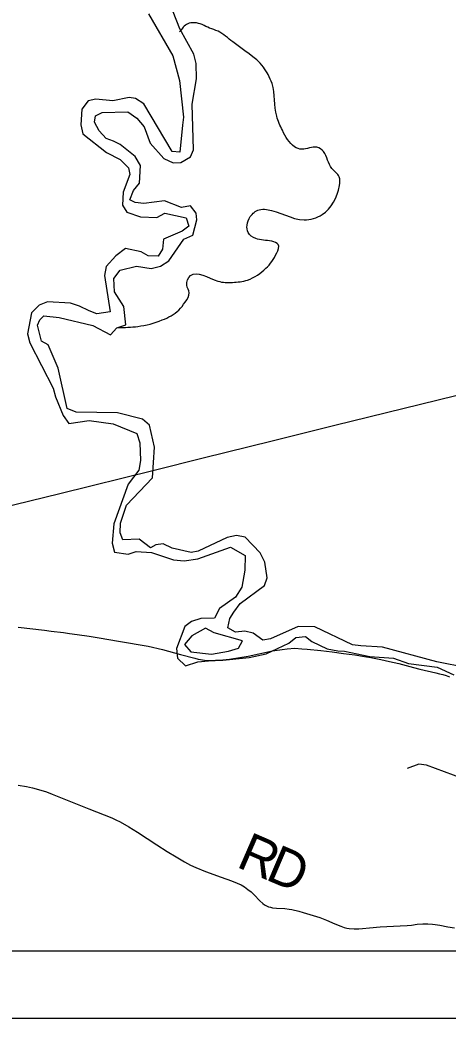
# Model space of a CAD drawing. Extents: x 0 to 34, y 0 to 22.
# Drawn here: x 4.8 to 5.439, y 14 to 15.488 of the extents above; entities that cross this region are included whole.
import ezdxf

# ---------------------------------------------------------------- set-up
doc = ezdxf.new("R2010")
doc.units = 0
for name, color, linetype in [('GM_X_Corporation', 7, 'Continuous'), ('GM_X_County_Road', 7, 'Continuous'), ('GM_X_Minor_River', 7, 'Continuous'), ('GM_X_Rail_Line', 7, 'Continuous'), ('GM_X_Township_Road', 7, 'Continuous'), ('GM_X_Township_Road_Text', 7, 'Continuous'), ('SH_Data', 7, 'Continuous')]:
    doc.layers.add(name, color=color, linetype=linetype)

msp = doc.modelspace()

# ---------------------------------------------------------------- linework, layer by layer
at = {"layer": 'GM_X_Corporation'}
for points in [[(2.1, 16.4477), (2.1, 14.1), (8.9, 14.1), (8.9, 16.2485)], [(2.1, 14.1), (5.9669, 14.1), (5.9718, 14.2339), (5.9719, 14.2518), (5.9912, 14.2433), (6.0106, 14.2347), (6.0457, 14.2204), (6.0638, 14.2101), (6.0897, 14.1893), (6.1001, 14.176), (6.1365, 14.1664), (6.1722, 14.163), (6.1971, 14.165), (6.2589, 14.1491), (6.3803, 14.132), (6.4075, 14.1583), (6.4485, 14.2016), (6.4833, 14.2331), (6.5212, 14.2247), (6.5417, 14.1767), (6.5313, 14.1149), (6.5592, 14.1021), (6.5997, 14.1245)]]:
    msp.add_lwpolyline(points, dxfattribs=at)
at = {"layer": 'GM_X_County_Road'}
msp.add_lwpolyline([(4.7978, 14.583), (4.8371, 14.5782), (4.847, 14.5769), (4.8651, 14.5746), (4.8743, 14.5735), (4.8855, 14.5719), (4.9034, 14.5694), (4.9185, 14.5667), (4.9472, 14.5621), (4.9917, 14.5544), (5.0129, 14.5496), (5.0399, 14.5422), (5.0608, 14.5364), (5.0662, 14.5351), (5.0694, 14.5344), (5.0756, 14.5337), (5.0852, 14.5332), (5.0913, 14.5332), (5.0976, 14.5334), (5.1129, 14.5351), (5.1404, 14.5397), (5.1769, 14.5473), (5.1913, 14.5494), (5.1989, 14.5504), (5.2103, 14.5513), (5.2206, 14.5507), (5.2286, 14.55), (5.249, 14.548), (5.266, 14.5459), (5.2827, 14.5437), (5.2994, 14.5413), (5.3141, 14.5389), (5.3236, 14.5374), (5.3386, 14.5347), (5.3513, 14.5318), (5.3651, 14.5285), (5.3873, 14.5226), (5.3964, 14.5201), (5.4206, 14.5148), (5.4259, 14.5134), (5.431, 14.512), (5.4356, 14.5106), (5.4406, 14.5089)], dxfattribs=at)
at = {"layer": 'GM_X_Minor_River'}
for points in [[(4.9921, 15.4975), (5.028, 15.4346), (5.0384, 15.3978), (5.0439, 15.3432), (5.0428, 15.3315), (5.0388, 15.2912), (5.0271, 15.292), (4.9848, 15.3631), (4.9726, 15.3711), (4.9631, 15.3725), (4.9389, 15.3675), (4.9132, 15.3701), (4.9022, 15.3678), (4.8924, 15.3552), (4.891, 15.3317), (4.8941, 15.3184), (4.9294, 15.2905), (4.9495, 15.2803), (4.9621, 15.2675), (4.964, 15.2576), (4.9543, 15.2314), (4.9532, 15.212), (4.9597, 15.2014), (4.9798, 15.1947), (5.0044, 15.1936), (5.0161, 15.2001), (5.048, 15.193), (5.0522, 15.1809), (5.042, 15.1733), (5.0144, 15.1614), (5.0126, 15.1462), (5.0066, 15.136), (4.9914, 15.1367), (4.9808, 15.1423), (4.9577, 15.1476), (4.943, 15.1365), (4.929, 15.1205), (4.9261, 15.1072)], [(4.9449, 15.0292), (4.9582, 15.0337), (4.9554, 15.0607), (4.9413, 15.083), (4.9401, 15.1027), (4.9499, 15.1153), (4.9741, 15.1211), (4.9957, 15.1177), (5.0097, 15.1212), (5.0225, 15.1292), (5.0447, 15.1615), (5.0579, 15.1673), (5.0642, 15.19), (5.0631, 15.1999), (5.0547, 15.2109), (5.0411, 15.2085), (5.0159, 15.2186), (4.9849, 15.2144), (4.9722, 15.2158), (4.9642, 15.22), (4.9698, 15.2341), (4.9785, 15.2448), (4.9799, 15.2713), (4.9722, 15.2846), (4.9498, 15.3023), (4.94, 15.3072), (4.929, 15.3113), (4.9183, 15.3227), (4.9114, 15.3356), (4.9129, 15.3451), (4.9231, 15.35), (4.961, 15.3513), (4.9746, 15.3419), (4.9857, 15.329), (4.9945, 15.3047), (5.015, 15.2817), (5.0287, 15.2753), (5.04, 15.2757), (5.0548, 15.2841), (5.0593, 15.2947), (5.0571, 15.3626), (5.0637, 15.4006), (5.0632, 15.423), (5.0598, 15.437), (5.0388, 15.4749), (5.0288, 15.5002)], [(4.9261, 15.1072), (4.9346, 15.053), (4.9149, 15.0499), (4.9036, 15.0544), (4.8892, 15.0612), (4.8755, 15.0657), (4.8414, 15.0679), (4.829, 15.0629), (4.8177, 15.0515), (4.8113, 15.0203), (4.8148, 15.0067), (4.8496, 14.9393), (4.8534, 14.926), (4.8645, 14.8984), (4.8733, 14.8863), (4.9035, 14.8909), (4.9391, 14.8861), (4.9744, 14.8714), (4.979, 14.8574), (4.9802, 14.8312), (4.9773, 14.8168), (4.9618, 14.7959), (4.9405, 14.737), (4.9376, 14.7082), (4.9411, 14.6945), (4.9615, 14.6916), (4.9736, 14.6958), (4.9963, 14.6943), (5.0096, 14.6895), (5.0293, 14.6831), (5.0449, 14.6816), (5.0657, 14.6847), (5.1144, 14.702), (5.1361, 14.6895), (5.1358, 14.6679), (5.131, 14.6424), (5.1216, 14.6276), (5.0978, 14.6108), (5.0906, 14.5964), (5.0698, 14.5956), (5.0562, 14.5913), (5.046, 14.5837), (5.0337, 14.5511), (5.0353, 14.5366), (5.047, 14.5249), (5.0656, 14.5311), (5.0921, 14.5334), (5.1027, 14.5335), (5.142, 14.5374), (5.1673, 14.5432), (5.201, 14.5588), (5.2115, 14.5676), (5.2259, 14.5688), (5.2354, 14.5612), (5.2582, 14.5507), (5.2741, 14.5477), (5.2843, 14.547), (5.3218, 14.5391), (5.3574, 14.5366), (5.3798, 14.5287), (5.4226, 14.5232), (5.4472, 14.5119)], [(5.4673, 14.5222), (5.4218, 14.5311), (5.3407, 14.5529), (5.3085, 14.555), (5.296, 14.5565), (5.2402, 14.5833), (5.2152, 14.5839), (5.1737, 14.5652), (5.1623, 14.5633), (5.1479, 14.5738), (5.1354, 14.5768), (5.1218, 14.5753), (5.1104, 14.5817), (5.113, 14.5957), (5.1194, 14.6052), (5.1288, 14.6182), (5.165, 14.6448), (5.1688, 14.6562), (5.1652, 14.6797), (5.1584, 14.6934), (5.1363, 14.7172), (5.1234, 14.7194), (5.1094, 14.7167), (5.066, 14.6961), (5.0558, 14.6942), (5.0274, 14.7005), (5.0137, 14.7069), (5.0027, 14.7057), (4.9947, 14.7011), (4.9778, 14.7138), (4.9539, 14.7132), (4.9497, 14.7234), (4.95, 14.7378), (4.9593, 14.7648), (4.9981, 14.8055), (5.001, 14.851), (4.9933, 14.884), (4.983, 14.8931), (4.9455, 14.9024), (4.8842, 14.9034), (4.8705, 14.909), (4.8574, 14.9689), (4.8421, 15.0038), (4.8326, 15.0094), (4.8263, 15.0333), (4.83, 15.0408), (4.8358, 15.047), (4.8589, 15.0444), (4.909, 15.0328), (4.9351, 15.0189), (4.9449, 15.0292)], [(5.09, 14.5744), (5.0767, 14.5812), (5.0567, 14.5701), (5.0454, 14.5568), (5.0553, 14.5462), (5.086, 14.5425), (5.1113, 14.5468)], [(5.1113, 14.5468), (5.126, 14.5514), (5.1321, 14.5624), (5.09, 14.5744)], [(5.8685, 14.2527), (5.868, 14.2236), (5.829, 14.2071), (5.7855, 14.177), (5.7727, 14.172), (5.7225, 14.1957), (5.71, 14.2039), (5.697, 14.2198), (5.6723, 14.2451), (5.6575, 14.253), (5.6445, 14.2655), (5.6229, 14.2726), (5.5986, 14.2759), (5.5621, 14.2909), (5.4948, 14.3381), (5.4849, 14.3445), (5.4735, 14.3524), (5.4063, 14.3771), (5.3953, 14.3786), (5.3779, 14.3721)]]:
    msp.add_lwpolyline(points, dxfattribs=at)
for points in [[(5.0831, 15.4758), (5.0603, 15.484), (5.0505, 15.4825), (5.0384, 15.4703)], [(4.9463, 15.0296), (4.976, 15.0312), (5.0123, 15.0408), (5.0372, 15.0556), (5.0466, 15.0674), (5.0526, 15.0815), (5.0491, 15.0925), (5.0544, 15.1069), (5.0953, 15.0987), (5.1173, 15.0969), (5.1396, 15.1004), (5.1671, 15.1179), (5.1833, 15.1408), (5.1855, 15.1533), (5.1757, 15.1582), (5.1518, 15.1623), (5.1404, 15.1713), (5.1389, 15.1823), (5.1437, 15.1949), (5.1569, 15.2052), (5.1679, 15.2056), (5.224, 15.1902), (5.2508, 15.1979), (5.2768, 15.2412), (5.2763, 15.2545), (5.2653, 15.2666), (5.2527, 15.292), (5.2432, 15.2984), (5.2205, 15.2953), (5.2099, 15.299), (5.1916, 15.3236), (5.1832, 15.3445), (5.1762, 15.3934), (5.1704, 15.4066), (5.1632, 15.418), (5.1176, 15.4554), (5.0956, 15.4713), (5.0831, 15.4758)]]:
    msp.add_spline(points, degree=3, dxfattribs=at)
at = {"layer": 'GM_X_Rail_Line'}
msp.add_lwpolyline([(4.7232, 14.7487), (4.8596, 14.7823), (5.0004, 14.8171), (5.0735, 14.8354), (5.1763, 14.8606), (5.27, 14.8838), (5.3976, 14.9152), (5.5295, 14.9475), (5.6419, 14.9754), (5.7924, 15.0128), (5.9194, 15.0442), (6.0332, 15.0721), (6.178, 15.108), (6.2632, 15.1289), (6.9157, 15.2894), (7.2078, 15.3612), (7.3771, 15.4031), (8.007, 15.5582), (8.6833, 15.725), (8.9, 15.7782)], dxfattribs=at)
at = {"layer": 'GM_X_Township_Road'}
msp.add_lwpolyline([(4.7976, 14.3472), (4.8098, 14.3452), (4.8189, 14.3433), (4.8279, 14.3409), (4.8397, 14.3372), (4.8484, 14.334), (4.883, 14.32), (4.9032, 14.3121), (4.9371, 14.2984), (4.9434, 14.2955), (4.9498, 14.2923), (4.9624, 14.285), (4.9757, 14.277), (5.0044, 14.2585), (5.0197, 14.2485), (5.0331, 14.2404), (5.0457, 14.2327), (5.0545, 14.2279), (5.0625, 14.2243), (5.077, 14.2183), (5.1005, 14.2102), (5.1158, 14.2048), (5.1244, 14.2012), (5.1299, 14.1985), (5.1352, 14.1954), (5.1403, 14.1919), (5.1451, 14.1881), (5.1496, 14.1839), (5.1581, 14.175), (5.1626, 14.1707), (5.1651, 14.1688), (5.1678, 14.1673), (5.1707, 14.166), (5.1737, 14.1651), (5.1768, 14.1645), (5.183, 14.1637), (5.1954, 14.1631), (5.2016, 14.1625), (5.2056, 14.1619), (5.216, 14.1594), (5.2225, 14.1575), (5.2326, 14.1545), (5.2476, 14.1497), (5.2575, 14.1458), (5.2697, 14.1405), (5.2787, 14.1368), (5.2835, 14.1349), (5.2878, 14.134), (5.2913, 14.1336), (5.2984, 14.133), (5.3057, 14.1331), (5.3113, 14.1336), (5.3213, 14.1343), (5.3372, 14.1359), (5.367, 14.1376), (5.3775, 14.1381), (5.3839, 14.1386), (5.3924, 14.1398), (5.401, 14.1404), (5.4087, 14.1405), (5.4152, 14.1401), (5.4193, 14.1395), (5.4262, 14.1384), (5.4385, 14.136), (5.4483, 14.1345)], dxfattribs=at)
at = {"layer": 'SH_Data'}
for p, q in [((2.1, 14.1), (8.9, 14.1)), ((2, 14), (9, 14))]:
    msp.add_line(p, q, dxfattribs=at)

# ---------------------------------------------------------------- texts
at = {"layer": 'GM_X_Township_Road_Text'}
for s, rotation, p in [('R', 336.4944, (5.1213, 14.2261)), ('D', 336.9391, (5.1646, 14.2073))]:
    msp.add_text(s, height=0.0568, rotation=rotation, dxfattribs=at).set_placement(p)

doc.saveas('drawing.dxf')
